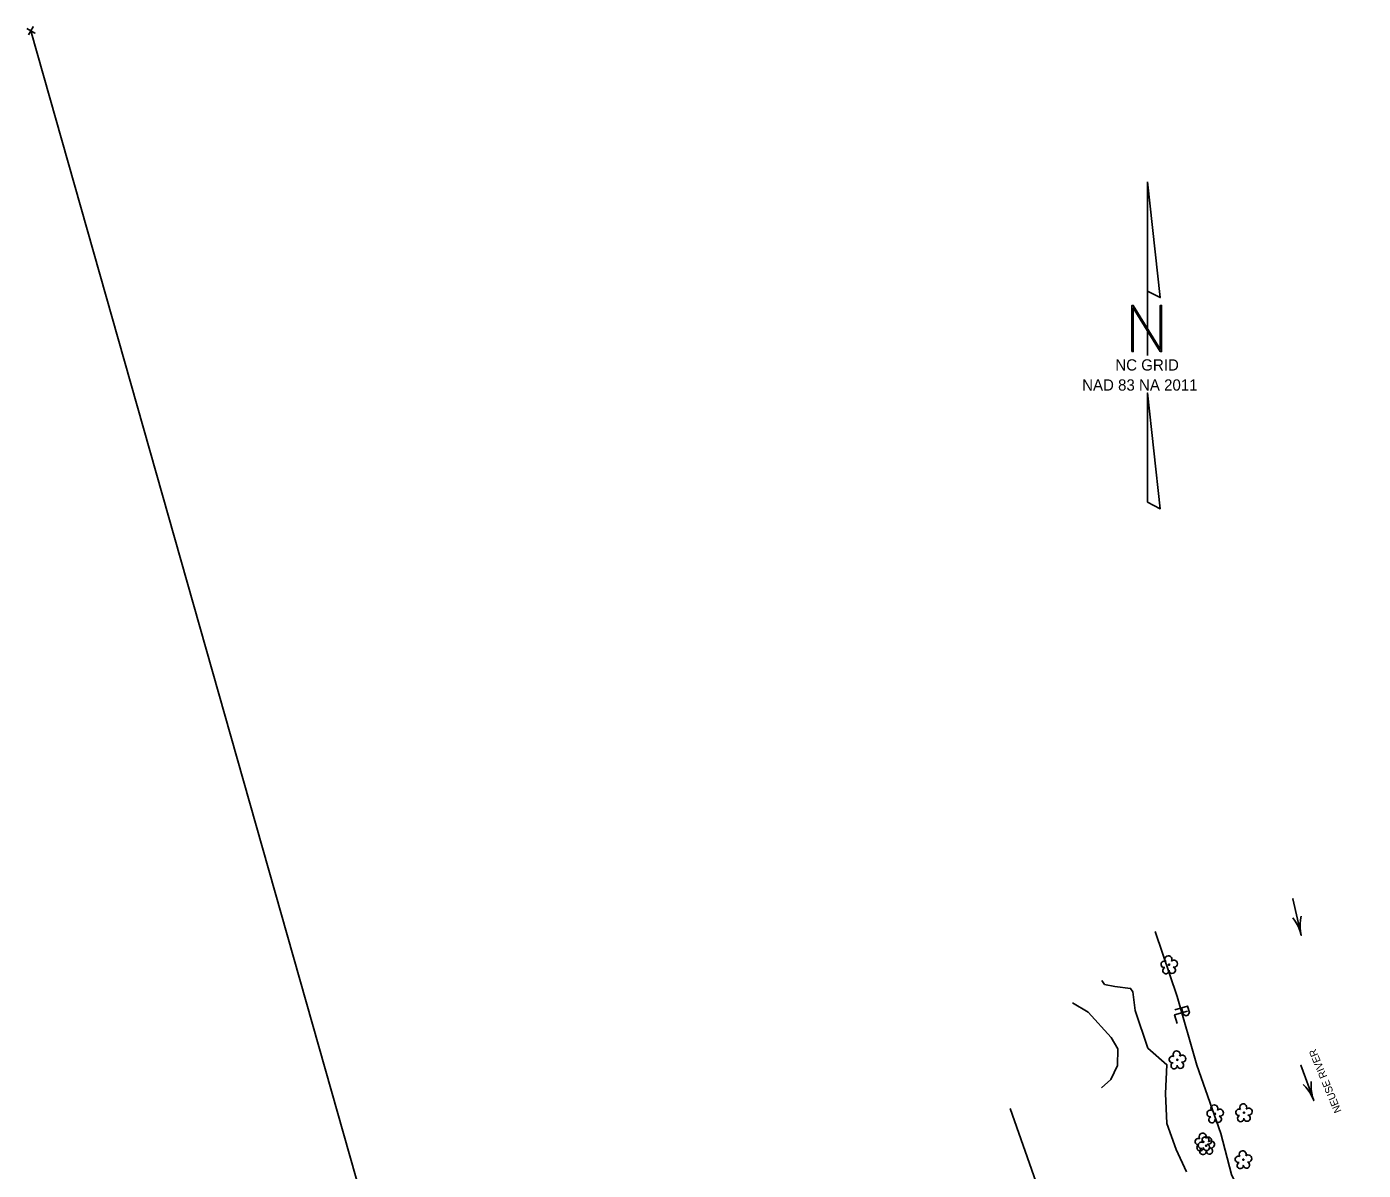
# Model space of a CAD drawing. Extents: x 2186615 to 2188822, y 629899 to 631820.
# Drawn here: x 2186929 to 2187642, y 630988 to 631598 of the extents above; entities that cross this region are included whole.
import ezdxf

# ---------------------------------------------------------------- set-up
doc = ezdxf.new("R2010")
doc.units = 0
for name, color, linetype in [('CTL North Arrow NAD 83 NA 2011 CELL', 7, 'Continuous'), ('Exist Hydro Jurisdictional Stream or Body of Water', 7, 'Continuous'), ('Exist Hydro Jurisdictional Stream or Body of Water Text', 7, 'Continuous'), ('Exist Hydro River Flow Arrow CELL', 7, 'Continuous'), ('Exist Hydro Stream or Body of Water', 7, 'Continuous'), ('Exist Property Corner CELL', 7, 'Continuous'), ('Exist Property Line', 7, 'Continuous'), ('Exist Property PL Symbol CELL', 7, 'Continuous'), ('Exist Vegetation Tree CELL', 7, 'Continuous'), ('Exist Vegetation Woods Line', 7, 'Continuous')]:
    doc.layers.add(name, color=color, linetype=linetype)

msp = doc.modelspace()

# ---------------------------------------------------------------- linework, layer by layer
at = {"layer": 'CTL North Arrow NAD 83 NA 2011 CELL'}
msp.add_line((2187526.59, 631427.92), (2187526.59, 631427.92), dxfattribs=at)
for points in [[(2187526.44, 631515.21), (2187526.44, 631456.88), (2187533.31, 631453.45)], [(2187518.21, 631424.66), (2187518.9, 631424.66), (2187518.9, 631447.98), (2187533.31, 631424.66), (2187534, 631424.66), (2187534, 631449.35), (2187533.31, 631449.35), (2187533.31, 631426.02), (2187518.9, 631449.35), (2187518.21, 631449.35)], [(2187526.44, 631344.37), (2187533.31, 631340.96), (2187526.44, 631402.7)]]:
    msp.add_lwpolyline(points, close=True, dxfattribs=at)
msp.add_lwpolyline([(2187526.44, 631456.88), (2187526.44, 631422.58)], dxfattribs=at)
at = {"layer": 'Exist Hydro Jurisdictional Stream or Body of Water'}
msp.add_lwpolyline([(2187641.56, 630778.99), (2187634.44, 630801.86), (2187629.98, 630815.05), (2187619.91, 630839.6), (2187614.17, 630860.83), (2187612.27, 630869.49), (2187608.82, 630885.82), (2187606.22, 630905.97), (2187595.59, 630933.27), (2187585.56, 630957.45), (2187571.29, 630986.1), (2187565.54, 631007.93), (2187552.83, 631044.44), (2187542.37, 631080.91), (2187530.56, 631115.64)], dxfattribs=at)
at = {"layer": 'Exist Hydro River Flow Arrow CELL'}
for p, q in [((2187606.29, 631123.33), (2187606.29, 631123.33)), ((2187611.72, 631034.89), (2187611.72, 631034.89))]:
    msp.add_line(p, q, dxfattribs=at)
for points in [[(2187608.52, 631123.84), (2187608.17, 631121.82), (2187607.99, 631119.75), (2187607.98, 631117.66), (2187608.14, 631115.59), (2187608.52, 631113.58), (2187604.06, 631133.08), (2187608.52, 631113.58), (2187607.99, 631115.56), (2187607.23, 631117.49), (2187606.31, 631119.37), (2187605.25, 631121.15), (2187604.06, 631122.82)], [(2187613.87, 631035.67), (2187613.77, 631033.62), (2187613.85, 631031.55), (2187614.1, 631029.47), (2187614.51, 631027.44), (2187615.14, 631025.49), (2187608.3, 631044.28), (2187615.14, 631025.49), (2187614.37, 631027.39), (2187613.37, 631029.21), (2187612.23, 631030.96), (2187610.96, 631032.6), (2187609.57, 631034.1)]]:
    msp.add_lwpolyline(points, dxfattribs=at)
at = {"layer": 'Exist Hydro Stream or Body of Water'}
msp.add_lwpolyline([(2187357.89, 630691.71), (2187368.32, 630702.66), (2187388.13, 630721.85), (2187417.64, 630747.36), (2187427.64, 630753.86), (2187437.61, 630755.03), (2187447.6, 630751.13), (2187463.94, 630747.03), (2187475.5, 630735.04), (2187486.51, 630735.28), (2187498.77, 630737.77), (2187511.25, 630741.72), (2187518.83, 630749.32), (2187524.1, 630768.61), (2187535.5, 630783.28), (2187526.88, 630828.24), (2187510.87, 630849.27), (2187499.79, 630850.01), (2187504, 630870.39), (2187511.71, 630896.5), (2187504.86, 630916.45), (2187478.39, 630945.02), (2187468.31, 630978.88), (2187453.32, 631021.21)], dxfattribs=at)
at = {"layer": 'Exist Property Corner CELL'}
msp.add_line((2186931.15, 631595.66), (2186931.15, 631595.66), dxfattribs=at)
msp.add_lwpolyline([(2186928.97, 631596.88), (2186933.34, 631594.44), (2186931.15, 631595.66), (2186932.37, 631597.84), (2186929.93, 631593.48)], dxfattribs=at)
at = {"layer": 'Exist Property Line'}
msp.add_line((2187243.29, 630495.73), (2186931.15, 631595.66), dxfattribs=at)
msp.add_lwpolyline([(2187637.7, 630791.42), (2187634.44, 630801.86), (2187629.98, 630815.05), (2187619.91, 630839.6), (2187614.17, 630860.83), (2187612.27, 630869.49), (2187608.82, 630885.82), (2187606.22, 630905.97), (2187595.59, 630933.27), (2187585.56, 630957.45), (2187571.29, 630986.1), (2187565.54, 631007.93), (2187552.83, 631044.44), (2187542.37, 631080.91), (2187530.56, 631115.64)], dxfattribs=at)
at = {"layer": 'Exist Property PL Symbol CELL'}
msp.add_line((2187544.53, 631073.38), (2187544.53, 631073.38), dxfattribs=at)
for points in [[(2187541.16, 631073.93), (2187547.91, 631075.86), (2187548.9, 631072.44), (2187548.09, 631071), (2187546.97, 631070.68), (2187545.59, 631071.49), (2187544.61, 631074.92)], [(2187547.8, 631073.14), (2187541, 631071.19), (2187542.3, 631066.65)]]:
    msp.add_lwpolyline(points, dxfattribs=at)
at = {"layer": 'Exist Vegetation Tree CELL'}
for p, q in [((2187538.04, 631097.9), (2187538.04, 631097.9)), ((2187542.45, 631047.23), (2187542.45, 631047.23)), ((2187562.57, 631018.44), (2187562.57, 631018.44)), ((2187577.95, 631019.03), (2187577.95, 631019.03)), ((2187556.3, 631003.48), (2187556.3, 631003.48)), ((2187557.83, 631001.48), (2187557.83, 631001.48)), ((2187577.64, 630994.02), (2187577.64, 630994.02))]:
    msp.add_line(p, q, dxfattribs=at)
for centre in [(2187538.04, 631097.9), (2187542.45, 631047.23), (2187562.57, 631018.44), (2187577.95, 631019.03), (2187556.3, 631003.48), (2187557.83, 631001.48), (2187577.64, 630994.02)]:
    msp.add_circle(centre, 0.326, dxfattribs=at)
for centre, radius, start, end in [((2187535.44, 631098.06), 1.73, 62.66361, 279.3457), ((2187536.34, 631094.78), 1.69, 111.56708, 6.23104), ((2187537.66, 631100.78), 1.86, 330.16508, 219.71335), ((2187539.71, 631095), 1.7, 181.28216, 74.55999), ((2187540.59, 631098.49), 1.9, 257.1011, 134.19993), ((2187539.84, 631047.39), 1.73, 62.66361, 279.3457), ((2187542.06, 631050.11), 1.86, 330.16508, 219.71335), ((2187545, 631047.82), 1.9, 257.1011, 134.19993), ((2187540.74, 631044.11), 1.69, 111.56708, 6.23104), ((2187544.12, 631044.33), 1.7, 181.28216, 74.55999), ((2187559.96, 631018.59), 1.73, 62.66361, 279.3457), ((2187562.18, 631021.31), 1.86, 330.16508, 219.71335), ((2187565.11, 631019.02), 1.9, 257.1011, 134.19993), ((2187575.35, 631019.19), 1.73, 62.66361, 279.3457), ((2187577.57, 631021.91), 1.86, 330.16508, 219.71335), ((2187579.62, 631016.13), 1.7, 181.28216, 74.55999), ((2187580.5, 631019.62), 1.9, 257.1011, 134.19993), ((2187560.86, 631015.31), 1.69, 111.56708, 6.23104), ((2187564.24, 631015.54), 1.7, 181.28216, 74.55999), ((2187576.25, 631015.91), 1.69, 111.56708, 6.23104), ((2187553.69, 631003.64), 1.73, 62.66361, 279.3457), ((2187555.91, 631006.35), 1.86, 330.16508, 219.71335), ((2187557.45, 631004.35), 1.86, 330.16508, 219.71335), ((2187558.85, 631004.07), 1.9, 257.1011, 134.19993), ((2187560.38, 631002.07), 1.9, 257.1011, 134.19993), ((2187554.59, 631000.36), 1.69, 111.56708, 6.23104), ((2187555.23, 631001.63), 1.73, 62.66361, 279.3457), ((2187556.13, 630998.36), 1.69, 111.56708, 6.23104), ((2187557.97, 631000.58), 1.7, 181.28216, 74.55999), ((2187559.5, 630998.58), 1.7, 181.28216, 74.55999), ((2187577.26, 630996.89), 1.86, 330.16508, 219.71335), ((2187580.19, 630994.61), 1.9, 257.1011, 134.19993), ((2187575.03, 630994.17), 1.73, 62.66361, 279.3457), ((2187575.94, 630990.9), 1.69, 111.56708, 6.23104), ((2187579.31, 630991.12), 1.7, 181.28216, 74.55999)]:
    msp.add_arc(centre, radius, start, end, dxfattribs=at)
at = {"layer": 'Exist Vegetation Woods Line'}
for points in [[(2187502.12, 631089.41), (2187503.66, 631087.4), (2187509.1, 631086.32), (2187517.5, 631085.3), (2187518.74, 631083.52), (2187519.99, 631073.43), (2187526.79, 631053.43), (2187536.9, 631044.57), (2187536.18, 631029.21), (2187536.83, 631013.28)], [(2187502.05, 631032.24), (2187507.04, 631036.64), (2187510.53, 631044.24), (2187510.64, 631053.08), (2187507.24, 631059.16), (2187494.96, 631072.62), (2187486.49, 631077.66)], [(2187536.83, 631013.28), (2187541.78, 630999.35), (2187547.35, 630987.43)]]:
    msp.add_lwpolyline(points, dxfattribs=at)

# ---------------------------------------------------------------- texts
at = {"layer": 'CTL North Arrow NAD 83 NA 2011 CELL'}
for s, p in [('NC GRID', (2187509.36, 631414.59)), ('NAD 83 NA 2011', (2187491.67, 631403.9))]:
    msp.add_text(s, height=6, dxfattribs=at).set_placement(p)
at = {"layer": 'Exist Hydro Jurisdictional Stream or Body of Water Text'}
msp.add_text('NEUSE RIVER', height=4, rotation=112.54562, dxfattribs=at).set_placement((2187630.04, 631019.89))

doc.saveas('drawing.dxf')
